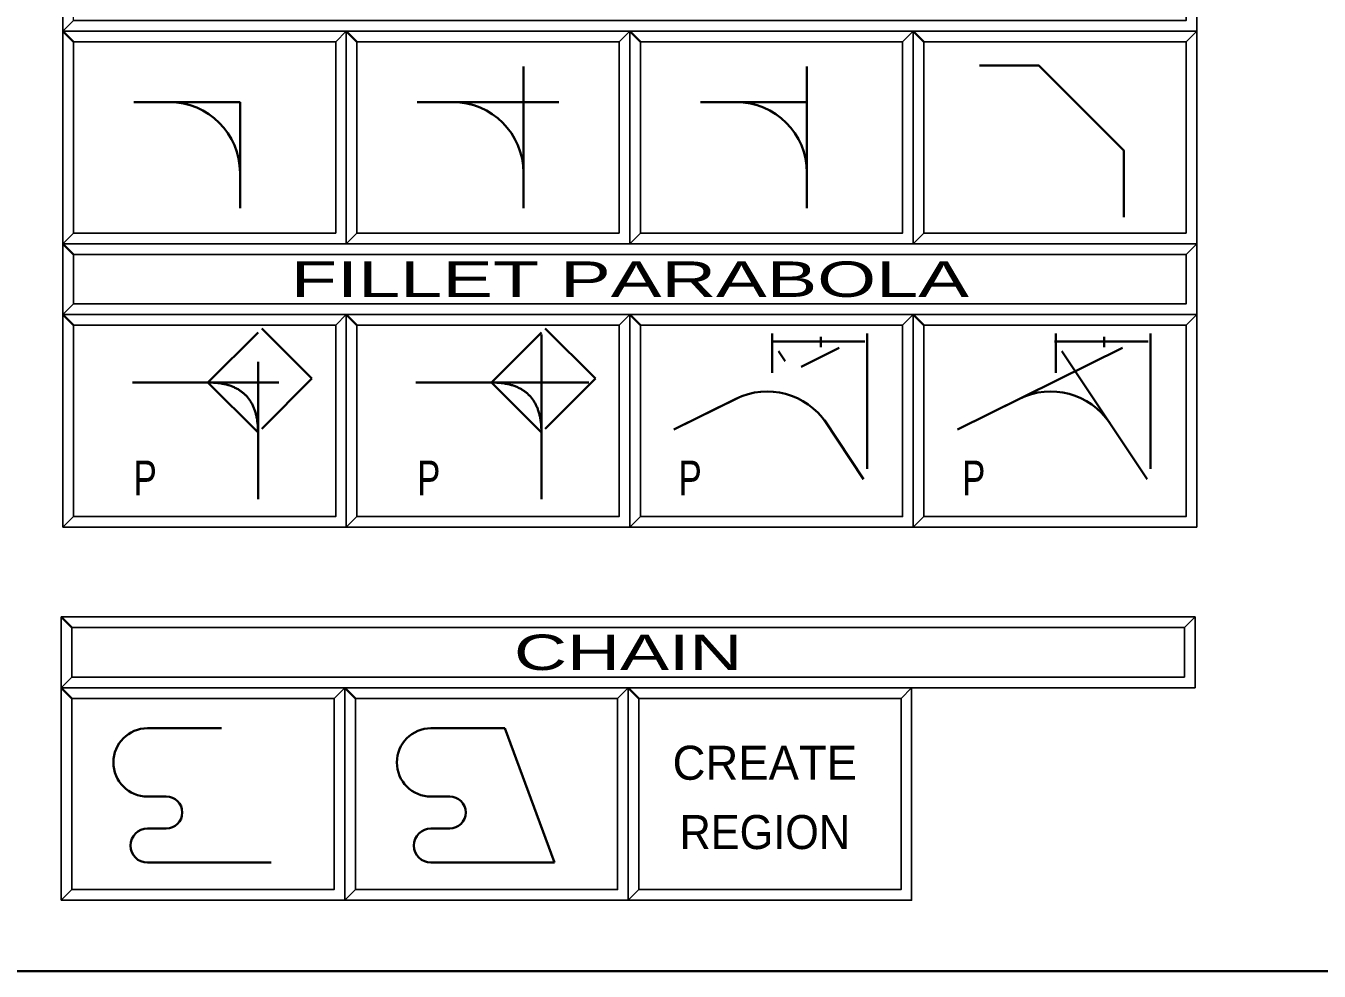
# Model space of a CAD drawing. Extents: x 95906.9 to 95918.9, y 90964.8 to 90972.9.
# Drawn here: x 95908.882 to 95910.707, y 90964.762 to 90966.096 of the extents above; entities that cross this region are included whole.
import ezdxf
from ezdxf.enums import TextEntityAlignment as Align

# ---------------------------------------------------------------- set-up
doc = ezdxf.new("R2010")
doc.units = 0
doc.header["$LTSCALE"] = 0.019
doc.linetypes.add('DOTTED', pattern=[1.5, 0.3, -1.2])
doc.linetypes.add('MEDIUM_DASHED', pattern=[4.5, 3, -1.5])
for name, color, linetype, lineweight in [('1', 7, 'Continuous', 25), ('11', 7, 'Continuous', 25), ('12', 7, 'Continuous', 25), ('18', 7, 'Continuous', 25), ('2', 7, 'Continuous', 13), ('3', 7, 'Continuous', 25), ('4', 7, 'Continuous', 35), ('6', 7, 'Continuous', 35), ('7', 7, 'Continuous', 35)]:
    doc.layers.add(name, color=color, linetype=linetype, lineweight=lineweight)

msp = doc.modelspace()

# ---------------------------------------------------------------- linework, layer by layer
at = {"layer": '1'}
for points in [[(95908.9345, 90966.0883), (95910.5345, 90966.0883), (95910.5345, 90966.1883), (95908.9345, 90966.1883)], [(95908.9345, 90965.7883), (95909.3345, 90965.7883), (95909.3345, 90966.0883), (95908.9345, 90966.0883)], [(95909.3345, 90965.7883), (95909.7345, 90965.7883), (95909.7345, 90966.0883), (95909.3345, 90966.0883)], [(95909.7345, 90965.7883), (95910.1345, 90965.7883), (95910.1345, 90966.0883), (95909.7345, 90966.0883)], [(95910.1345, 90965.7883), (95910.5345, 90965.7883), (95910.5345, 90966.0883), (95910.1345, 90966.0883)], [(95908.9345, 90965.6883), (95910.5345, 90965.6883), (95910.5345, 90965.7883), (95908.9345, 90965.7883)], [(95908.9345, 90965.3883), (95909.3345, 90965.3883), (95909.3345, 90965.6883), (95908.9345, 90965.6883)], [(95909.3345, 90965.3883), (95909.7345, 90965.3883), (95909.7345, 90965.6883), (95909.3345, 90965.6883)], [(95909.7345, 90965.3883), (95910.1345, 90965.3883), (95910.1345, 90965.6883), (95909.7345, 90965.6883)], [(95910.1345, 90965.3883), (95910.5345, 90965.3883), (95910.5345, 90965.6883), (95910.1345, 90965.6883)], [(95908.9323, 90965.1617), (95910.5323, 90965.1617), (95910.5323, 90965.2617), (95908.9323, 90965.2617)], [(95908.9323, 90964.8617), (95909.3323, 90964.8617), (95909.3323, 90965.1617), (95908.9323, 90965.1617)], [(95909.3323, 90964.8617), (95909.7323, 90964.8617), (95909.7323, 90965.1617), (95909.3323, 90965.1617)], [(95909.7323, 90964.8617), (95910.1323, 90964.8617), (95910.1323, 90965.1617), (95909.7323, 90965.1617)]]:
    msp.add_lwpolyline(points, close=True, dxfattribs=at)
at = {"layer": '11'}
for points in [[(95908.9495, 90965.8033), (95909.3195, 90965.8033), (95909.3195, 90966.0733), (95908.9495, 90966.0733)], [(95909.3495, 90965.8033), (95909.7195, 90965.8033), (95909.7195, 90966.0733), (95909.3495, 90966.0733)], [(95909.7495, 90965.8033), (95910.1195, 90965.8033), (95910.1195, 90966.0733), (95909.7495, 90966.0733)], [(95910.1495, 90965.8033), (95910.5195, 90965.8033), (95910.5195, 90966.0733), (95910.1495, 90966.0733)], [(95908.9495, 90965.4033), (95909.3195, 90965.4033), (95909.3195, 90965.6733), (95908.9495, 90965.6733)], [(95909.3495, 90965.4033), (95909.7195, 90965.4033), (95909.7195, 90965.6733), (95909.3495, 90965.6733)], [(95909.7495, 90965.4033), (95910.1195, 90965.4033), (95910.1195, 90965.6733), (95909.7495, 90965.6733)], [(95910.1495, 90965.4033), (95910.5195, 90965.4033), (95910.5195, 90965.6733), (95910.1495, 90965.6733)], [(95908.9473, 90964.8767), (95909.3173, 90964.8767), (95909.3173, 90965.1467), (95908.9473, 90965.1467)], [(95909.3473, 90964.8767), (95909.7173, 90964.8767), (95909.7173, 90965.1467), (95909.3473, 90965.1467)], [(95909.7473, 90964.8767), (95910.1173, 90964.8767), (95910.1173, 90965.1467), (95909.7473, 90965.1467)]]:
    msp.add_lwpolyline(points, close=True, dxfattribs=at)
at = {"layer": '12'}
for points in [[(95908.9495, 90965.8033), (95909.3195, 90965.8033), (95909.3195, 90966.0733), (95908.9495, 90966.0733)], [(95908.9473, 90964.8767), (95909.3173, 90964.8767), (95909.3173, 90965.1467), (95908.9473, 90965.1467)]]:
    msp.add_lwpolyline(points, close=True, dxfattribs=at)
at = {"layer": '18'}
for points in [[(95908.9495, 90965.7033), (95910.5195, 90965.7033), (95910.5195, 90965.7733), (95908.9495, 90965.7733)], [(95908.9473, 90965.1767), (95910.5173, 90965.1767), (95910.5173, 90965.2467), (95908.9473, 90965.2467)]]:
    msp.add_lwpolyline(points, close=True, dxfattribs=at)
at = {"layer": '2'}
for points in [[(95908.9345, 90966.1883), (95908.9345, 90966.0883), (95908.9495, 90966.1033), (95908.9495, 90966.1733), (95910.5195, 90966.1733), (95910.5345, 90966.1883)], [(95908.9345, 90966.0883), (95908.9345, 90965.7883), (95908.9495, 90965.8033), (95908.9495, 90966.0733), (95909.3195, 90966.0733), (95909.3345, 90966.0883)], [(95909.3345, 90966.0883), (95909.3345, 90965.7883), (95909.3495, 90965.8033), (95909.3495, 90966.0733), (95909.7195, 90966.0733), (95909.7345, 90966.0883)], [(95909.7345, 90966.0883), (95909.7345, 90965.7883), (95909.7495, 90965.8033), (95909.7495, 90966.0733), (95910.1195, 90966.0733), (95910.1345, 90966.0883)], [(95910.1345, 90966.0883), (95910.1345, 90965.7883), (95910.1495, 90965.8033), (95910.1495, 90966.0733), (95910.5195, 90966.0733), (95910.5345, 90966.0883)], [(95908.9345, 90965.7883), (95908.9345, 90965.6883), (95908.9495, 90965.7033), (95908.9495, 90965.7733), (95910.5195, 90965.7733), (95910.5345, 90965.7883)], [(95908.9345, 90965.6883), (95908.9345, 90965.3883), (95908.9495, 90965.4033), (95908.9495, 90965.6733), (95909.3195, 90965.6733), (95909.3345, 90965.6883)], [(95909.3345, 90965.6883), (95909.3345, 90965.3883), (95909.3495, 90965.4033), (95909.3495, 90965.6733), (95909.7195, 90965.6733), (95909.7345, 90965.6883)], [(95909.7345, 90965.6883), (95909.7345, 90965.3883), (95909.7495, 90965.4033), (95909.7495, 90965.6733), (95910.1195, 90965.6733), (95910.1345, 90965.6883)], [(95910.1345, 90965.6883), (95910.1345, 90965.3883), (95910.1495, 90965.4033), (95910.1495, 90965.6733), (95910.5195, 90965.6733), (95910.5345, 90965.6883)], [(95908.9323, 90965.2617), (95908.9323, 90965.1617), (95908.9473, 90965.1767), (95908.9473, 90965.2467), (95910.5173, 90965.2467), (95910.5323, 90965.2617)], [(95908.9323, 90965.1617), (95908.9323, 90964.8617), (95908.9473, 90964.8767), (95908.9473, 90965.1467), (95909.3173, 90965.1467), (95909.3323, 90965.1617)], [(95909.3323, 90965.1617), (95909.3323, 90964.8617), (95909.3473, 90964.8767), (95909.3473, 90965.1467), (95909.7173, 90965.1467), (95909.7323, 90965.1617)], [(95909.7323, 90965.1617), (95909.7323, 90964.8617), (95909.7473, 90964.8767), (95909.7473, 90965.1467), (95910.1173, 90965.1467), (95910.1323, 90965.1617)]]:
    msp.add_lwpolyline(points, close=True, dxfattribs=at)
at = {"layer": '3'}
for points in [[(95908.9345, 90966.0883), (95910.5345, 90966.0883), (95910.5345, 90966.1883), (95910.5195, 90966.1733), (95910.5195, 90966.1033), (95908.9495, 90966.1033)], [(95908.9345, 90965.7883), (95909.3345, 90965.7883), (95909.3345, 90966.0883), (95909.3195, 90966.0733), (95909.3195, 90965.8033), (95908.9495, 90965.8033)], [(95909.3345, 90965.7883), (95909.7345, 90965.7883), (95909.7345, 90966.0883), (95909.7195, 90966.0733), (95909.7195, 90965.8033), (95909.3495, 90965.8033)], [(95909.7345, 90965.7883), (95910.1345, 90965.7883), (95910.1345, 90966.0883), (95910.1195, 90966.0733), (95910.1195, 90965.8033), (95909.7495, 90965.8033)], [(95910.1345, 90965.7883), (95910.5345, 90965.7883), (95910.5345, 90966.0883), (95910.5195, 90966.0733), (95910.5195, 90965.8033), (95910.1495, 90965.8033)], [(95908.9345, 90965.6883), (95910.5345, 90965.6883), (95910.5345, 90965.7883), (95910.5195, 90965.7733), (95910.5195, 90965.7033), (95908.9495, 90965.7033)], [(95908.9345, 90965.3883), (95909.3345, 90965.3883), (95909.3345, 90965.6883), (95909.3195, 90965.6733), (95909.3195, 90965.4033), (95908.9495, 90965.4033)], [(95909.3345, 90965.3883), (95909.7345, 90965.3883), (95909.7345, 90965.6883), (95909.7195, 90965.6733), (95909.7195, 90965.4033), (95909.3495, 90965.4033)], [(95909.7345, 90965.3883), (95910.1345, 90965.3883), (95910.1345, 90965.6883), (95910.1195, 90965.6733), (95910.1195, 90965.4033), (95909.7495, 90965.4033)], [(95910.1345, 90965.3883), (95910.5345, 90965.3883), (95910.5345, 90965.6883), (95910.5195, 90965.6733), (95910.5195, 90965.4033), (95910.1495, 90965.4033)], [(95908.9323, 90965.1617), (95910.5323, 90965.1617), (95910.5323, 90965.2617), (95910.5173, 90965.2467), (95910.5173, 90965.1767), (95908.9473, 90965.1767)], [(95908.9323, 90964.8617), (95909.3323, 90964.8617), (95909.3323, 90965.1617), (95909.3173, 90965.1467), (95909.3173, 90964.8767), (95908.9473, 90964.8767)], [(95909.3323, 90964.8617), (95909.7323, 90964.8617), (95909.7323, 90965.1617), (95909.7173, 90965.1467), (95909.7173, 90964.8767), (95909.3473, 90964.8767)], [(95909.7323, 90964.8617), (95910.1323, 90964.8617), (95910.1323, 90965.1617), (95910.1173, 90965.1467), (95910.1173, 90964.8767), (95909.7473, 90964.8767)]]:
    msp.add_lwpolyline(points, close=True, dxfattribs=at)
at = {"layer": '4'}
for p, q in [((95908.9495, 90966.0733), (95908.9345, 90966.0883)), ((95909.3495, 90966.0733), (95909.3345, 90966.0883)), ((95909.7495, 90966.0733), (95909.7345, 90966.0883)), ((95910.1495, 90966.0733), (95910.1345, 90966.0883)), ((95908.9495, 90965.7733), (95908.9345, 90965.7883)), ((95908.9495, 90965.6733), (95908.9345, 90965.6883)), ((95909.3495, 90965.6733), (95909.3345, 90965.6883)), ((95909.7495, 90965.6733), (95909.7345, 90965.6883)), ((95910.1495, 90965.6733), (95910.1345, 90965.6883)), ((95908.9473, 90965.2467), (95908.9323, 90965.2617)), ((95908.9473, 90965.1467), (95908.9323, 90965.1617)), ((95909.3473, 90965.1467), (95909.3323, 90965.1617)), ((95909.7473, 90965.1467), (95909.7323, 90965.1617))]:
    msp.add_line(p, q, dxfattribs=at)
at = {"layer": '6', "linetype": 'MEDIUM_DASHED'}
for p, q in [((95909.1845, 90965.8883), (95909.1845, 90966.0383)), ((95909.0845, 90965.9883), (95909.2345, 90965.9883)), ((95909.0845, 90965.9883), (95909.2345, 90965.9883)), ((95909.8845, 90965.9883), (95910.0345, 90965.9883))]:
    msp.add_line(p, q, dxfattribs=at)
at = {"layer": '6'}
for p, q in [((95909.5845, 90965.8383), (95909.5845, 90966.0383)), ((95909.9845, 90965.8883), (95909.9845, 90966.0383)), ((95909.0345, 90965.9883), (95909.0845, 90965.9883)), ((95909.4345, 90965.9883), (95909.6345, 90965.9883)), ((95909.8345, 90965.9883), (95909.8845, 90965.9883)), ((95909.1845, 90965.8383), (95909.1845, 90965.8883)), ((95909.9845, 90965.8383), (95909.9845, 90965.8883)), ((95909.6099, 90965.5218), (95909.6099, 90965.6601)), ((95909.9339, 90965.6503), (95910.0662, 90965.6503)), ((95909.9356, 90965.6062), (95909.9356, 90965.6617)), ((95910.0041, 90965.6421), (95910.0041, 90965.6568)), ((95910.0694, 90965.4707), (95910.0694, 90965.6617)), ((95910.3339, 90965.6503), (95910.4662, 90965.6503)), ((95910.3356, 90965.6062), (95910.3356, 90965.6617)), ((95910.4041, 90965.6421), (95910.4041, 90965.6568)), ((95910.4694, 90965.4707), (95910.4694, 90965.6617)), ((95910.1968, 90965.5262), (95910.43, 90965.6413)), ((95910.4645, 90965.4561), (95910.3444, 90965.6366)), ((95909.0328, 90965.5925), (95909.1392, 90965.5925)), ((95909.4328, 90965.5925), (95909.5392, 90965.5925)), ((95909.5392, 90965.5925), (95909.6768, 90965.5925)), ((95909.7968, 90965.5262), (95909.8843, 90965.5694)), ((95910.1968, 90965.5262), (95910.2843, 90965.5694)), ((95909.2099, 90965.4276), (95909.2099, 90965.5218)), ((95909.6099, 90965.4276), (95909.6099, 90965.5218)), ((95910.0645, 90965.4561), (95910.0118, 90965.5353)), ((95910.4645, 90965.4561), (95910.4118, 90965.5353)), ((95909.1582, 90965.1045), (95909.054, 90965.1045)), ((95909.5582, 90965.1045), (95909.454, 90965.1045)), ((95909.5582, 90965.1045), (95909.6283, 90964.9148)), ((95909.054, 90965.0081), (95909.0804, 90965.0081)), ((95909.454, 90965.0081), (95909.4804, 90965.0081)), ((95909.0804, 90964.963), (95909.054, 90964.963)), ((95909.4804, 90964.963), (95909.454, 90964.963)), ((95909.054, 90964.9148), (95909.2283, 90964.9148)), ((95909.454, 90964.9148), (95909.6283, 90964.9148))]:
    msp.add_line(p, q, dxfattribs=at)
at = {"layer": '6', "linetype": 'DOTTED'}
for p, q in [((95909.2099, 90965.5218), (95909.2099, 90965.6601)), ((95909.7968, 90965.5262), (95910.03, 90965.6413)), ((95910.0645, 90965.4561), (95909.9444, 90965.6366)), ((95909.1392, 90965.5925), (95909.2768, 90965.5925))]:
    msp.add_line(p, q, dxfattribs=at)
at = {"layer": '6'}
msp.add_lwpolyline([(95910.2279, 90966.0397), (95910.3118, 90966.0397), (95910.4318, 90965.9197), (95910.4318, 90965.8258)], dxfattribs=at)
at = {"layer": '6', "linetype": 'DOTTED'}
for points in [[(95909.2099, 90965.5218), (95909.1392, 90965.5925), (95909.2153, 90965.6686), (95909.286, 90965.5979)], [(95909.6099, 90965.5218), (95909.5392, 90965.5925), (95909.6153, 90965.6686), (95909.686, 90965.5979)]]:
    msp.add_lwpolyline(points, close=True, dxfattribs=at)
at = {"layer": '6'}
for centre, radius, start, end in [((95909.0845, 90965.8883), 0.1, 0, 90), ((95909.0845, 90965.8883), 0.1, 0, 90), ((95909.4845, 90965.8883), 0.1, 0, 90), ((95909.8845, 90965.8883), 0.1, 0, 90), ((95909.9286, 90965.4798), 0.1, 33.7228, 116.3032), ((95910.3286, 90965.4798), 0.1, 33.7228, 116.3032), ((95909.054, 90965.0563), 0.0482, 90, 270), ((95909.454, 90965.0563), 0.0482, 90, 270), ((95909.0804, 90964.9856), 0.0226, 270, 90), ((95909.4804, 90964.9856), 0.0226, 270, 90), ((95909.054, 90964.9389), 0.0241, 90, 270), ((95909.454, 90964.9389), 0.0241, 90, 270)]:
    msp.add_arc(centre, radius, start, end, dxfattribs=at)
for points in [[(95909.2099, 90965.5218), (95909.2099, 90965.5251), (95909.2097, 90965.5284), (95909.2095, 90965.5315), (95909.2093, 90965.5346), (95909.2089, 90965.5376), (95909.2085, 90965.5405), (95909.2079, 90965.5434), (95909.2073, 90965.5462), (95909.2067, 90965.5488), (95909.2059, 90965.5515), (95909.205, 90965.554), (95909.2041, 90965.5564), (95909.2031, 90965.5588), (95909.202, 90965.5611), (95909.2009, 90965.5633), (95909.1996, 90965.5654), (95909.1983, 90965.5674), (95909.1969, 90965.5694), (95909.1954, 90965.5713), (95909.1939, 90965.5731), (95909.1922, 90965.5748), (95909.1905, 90965.5765), (95909.1887, 90965.578), (95909.1868, 90965.5795), (95909.1848, 90965.5809), (95909.1828, 90965.5822), (95909.1807, 90965.5835), (95909.1785, 90965.5846), (95909.1762, 90965.5857), (95909.1738, 90965.5867), (95909.1714, 90965.5876), (95909.1689, 90965.5885), (95909.1662, 90965.5893), (95909.1636, 90965.5899), (95909.1608, 90965.5905), (95909.1579, 90965.5911), (95909.155, 90965.5915), (95909.152, 90965.5919), (95909.1489, 90965.5921), (95909.1458, 90965.5923), (95909.1425, 90965.5925), (95909.1392, 90965.5925)], [(95909.6099, 90965.5218), (95909.6099, 90965.5251), (95909.6097, 90965.5284), (95909.6095, 90965.5315), (95909.6093, 90965.5346), (95909.6089, 90965.5376), (95909.6085, 90965.5405), (95909.6079, 90965.5434), (95909.6073, 90965.5462), (95909.6067, 90965.5488), (95909.6059, 90965.5515), (95909.605, 90965.554), (95909.6041, 90965.5564), (95909.6031, 90965.5588), (95909.602, 90965.5611), (95909.6009, 90965.5633), (95909.5996, 90965.5654), (95909.5983, 90965.5674), (95909.5969, 90965.5694), (95909.5954, 90965.5713), (95909.5939, 90965.5731), (95909.5922, 90965.5748), (95909.5905, 90965.5765), (95909.5887, 90965.578), (95909.5868, 90965.5795), (95909.5848, 90965.5809), (95909.5828, 90965.5822), (95909.5807, 90965.5835), (95909.5785, 90965.5846), (95909.5762, 90965.5857), (95909.5738, 90965.5867), (95909.5714, 90965.5876), (95909.5689, 90965.5885), (95909.5662, 90965.5893), (95909.5636, 90965.5899), (95909.5608, 90965.5905), (95909.5579, 90965.5911), (95909.555, 90965.5915), (95909.552, 90965.5919), (95909.5489, 90965.5921), (95909.5458, 90965.5923), (95909.5425, 90965.5925), (95909.5392, 90965.5925)]]:
    msp.add_spline(points, degree=3, dxfattribs=at)
at = {"layer": '7'}
msp.add_lwpolyline([(95906.8548, 90972.8617), (95918.8548, 90972.8617), (95918.8548, 90964.7617), (95906.8548, 90964.7617)], close=True, dxfattribs=at)

# ---------------------------------------------------------------- texts
at = {"layer": '6'}
for s, height, width, p in [('P', 0.0491, 0.75, (95909.0507, 90965.4331)), ('P', 0.0491, 0.75, (95909.4508, 90965.4331)), ('P', 0.0491, 0.75, (95909.8197, 90965.4331)), ('P', 0.0491, 0.75, (95910.2199, 90965.4331)), ('REGION', 0.048, 0.95, (95909.9251, 90964.934))]:
    msp.add_text(s, height=height, dxfattribs=dict(at, width=width)).set_placement(p, align=Align.CENTER)
msp.add_text('CREATE', height=0.048, dxfattribs=at).set_placement((95909.9251, 90965.0318), align=Align.CENTER)
at = {"layer": '7'}
for s, width, p in [('    FILLET PARABOLA    ', 1.6, (95909.7345, 90965.7133)), ('         CHAIN         ', 1.55, (95909.7323, 90965.1867))]:
    msp.add_text(s, height=0.04999, dxfattribs=dict(at, width=width)).set_placement(p, align=Align.CENTER)

doc.saveas('drawing.dxf')
